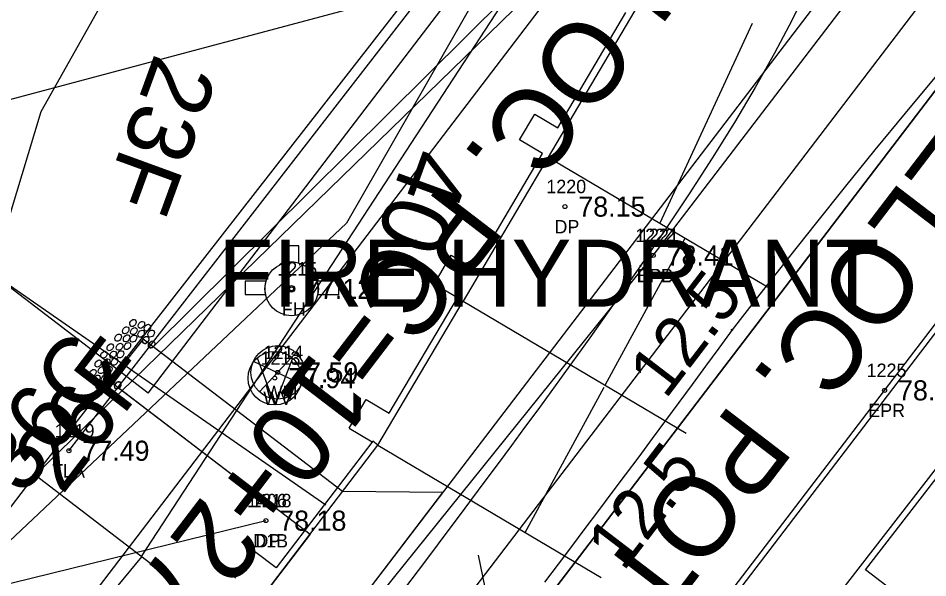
# Model space of a CAD drawing. Extents: x 2500794 to 2511032, y 910653 to 917533.
# Drawn here: x 2506136.2 to 2506204.2, y 913995.8 to 914037.6 of the extents above; entities that cross this region are included whole.
import ezdxf

# ---------------------------------------------------------------- set-up
doc = ezdxf.new("R2010")
doc.units = 0
for name, color, linetype in [('Default', 7, 'Continuous'), ('RD_EX_Driveway', 7, 'Continuous'), ('RD_EX_Driveway_txCode', 7, 'Continuous'), ('RD_EX_H2O_txCode', 7, 'Continuous'), ('RD_EX_Road', 7, 'Continuous'), ('RD_EX_Road_txCode', 7, 'Continuous'), ('RD_EX_RW', 7, 'Continuous'), ('RD_EX_TX_Driveway_ELEV', 7, 'Continuous'), ('RD_EX_TX_Road_ELEV', 7, 'Continuous'), ('RD_EX_TX_UT_ELEV', 7, 'Continuous'), ('RD_EX_TX_VEG_ELEV', 7, 'Continuous'), ('RD_EX_UT', 7, 'Continuous'), ('RD_EX_UT_txCode', 7, 'Continuous'), ('RD_EX_VEG', 7, 'Continuous'), ('RD_EX_VEG_txCode', 7, 'Continuous'), ('RD_HC_Cl', 7, 'Continuous'), ('RD_HC_Data_Rel', 7, 'Continuous'), ('RD_HC_Data_Tic', 7, 'Continuous'), ('RD_PD_ALT1_TnTmp', 7, 'Continuous'), ('RD_PD_ALT1_TrvlWay', 7, 'Continuous'), ('RD_PD_CstnLmt', 7, 'Continuous'), ('RD_PD_CstnLmt_TX', 7, 'Continuous'), ('RD_PD_Detour', 7, 'Continuous'), ('RD_PD_GR', 7, 'Continuous'), ('RD_PD_MedBWall', 7, 'Continuous'), ('RD_PD_PaintMed', 7, 'Continuous'), ('RD_PD_PaveShd', 7, 'Continuous'), ('RD_PD_Signals', 7, 'Continuous'), ('RD_Sketch10', 7, 'Continuous'), ('RD_SMD_Locator', 7, 'Continuous')]:
    doc.layers.add(name, color=color, linetype=linetype)

# ---------------------------------------------------------------- blocks, each defined once
blk = doc.blocks.new('POINT_DISPLAY')
at = {"layer": 'Default'}
blk.add_line((0, 0), (0, 0), dxfattribs=at)

msp = doc.modelspace()

# ---------------------------------------------------------------- linework, layer by layer
at = {"layer": 'RD_EX_Driveway'}
msp.add_lwpolyline([(2505985.767, 913963.589), (2506043.743, 913975.78), (2506109.597, 913989.049), (2506154.744, 914000.103)], dxfattribs=at)
at = {"layer": 'RD_EX_H2O_txCode'}
msp.add_lwpolyline([(2506111.845, 914025.213), (2506191.122, 914046.339), (2506240.906, 914108.602), (2506304.096, 914190.052), (2506361.191, 914264.825), (2506427.45, 914348.312), (2506450.333, 914379.52)], dxfattribs=at)
at = {"layer": 'RD_EX_Road'}
for points in [[(2506114.007, 913933.801), (2506123.607, 913945.349), (2506183.697, 914019.9), (2506246.754, 914102.24), (2506309.518, 914184.625), (2506366.784, 914260.378), (2506431.546, 914345.252), (2506455.95, 914376.736), (2506469.753, 914395.23), (2506492.702, 914425.08), (2506555.841, 914508.256), (2506617.748, 914589.016), (2506679.77, 914670.808), (2506740.348, 914750.219)], [(2506132.308, 913920.136), (2506200.992, 914009.83), (2506228.777, 914046.137), (2506238.188, 914058.362), (2506261.832, 914089.97), (2506324.496, 914172.224), (2506382.844, 914247.971), (2506424.88, 914303.725), (2506446.395, 914331.894), (2506508.342, 914413.092), (2506571.207, 914495.532), (2506633.007, 914576.806), (2506694.833, 914657.947), (2506756.779, 914739.179)]]:
    msp.add_lwpolyline(points, dxfattribs=at)
at = {"layer": 'RD_EX_RW'}
for q in [(2506722.671, 914763.958), (2506112.584, 914035.129)]:
    msp.add_line((2506145.95, 914009.619), q, dxfattribs=at)
at = {"layer": 'RD_EX_UT'}
for p, q in [((2506156.208, 914020.626), (2506156.208, 914019.352)), ((2506157.208, 914020.626), (2506156.208, 914020.626)), ((2506157.208, 914019.33), (2506157.208, 914020.626)), ((2506154.749, 914017.979), (2506153.192, 914017.979)), ((2506153.192, 914017.979), (2506153.192, 914016.979)), ((2506160.192, 914017.979), (2506158.581, 914017.979)), ((2506160.192, 914016.979), (2506160.192, 914017.979)), ((2506153.192, 914016.979), (2506154.711, 914016.979)), ((2506158.619, 914016.979), (2506160.192, 914016.979)), ((2506154.279, 914009.714), (2506156.946, 914012.611)), ((2506153.797, 914012.01), (2506157.428, 914010.297)), ((2506155.41, 914008.749), (2506154.106, 914012.232)), ((2506155.41, 914008.749), (2506156.732, 914012.194))]:
    msp.add_line(p, q, dxfattribs=at)
for centre, radius in [((2506156.665, 914017.405), 2), ((2506156.665, 914017.405), 0.25), ((2506155.41, 914010.742), 2), ((2506155.631, 914011.172), 2)]:
    msp.add_circle(centre, radius, dxfattribs=at)
for start, end in [(74.24553, 103.21276), (163.3387, 192.31502), (347.68498, 16.6613)]:
    msp.add_arc((2506156.665, 914017.405), 2, start, end, dxfattribs=at)
at = {"layer": 'RD_EX_VEG'}
msp.add_line((2506140.026, 914005.323), (2506726.018, 914761.038), dxfattribs=at)
at = {"layer": 'RD_HC_Cl'}
msp.add_line((2505807.568, 913512.69), (2506748.887, 914743.915), dxfattribs=at)
at = {"layer": 'RD_HC_Data_Rel'}
for p, q in [((2506234.439, 914115.768), (2506136.125, 913987.174)), ((2506256.026, 914099.264), (2506153.676, 913965.392))]:
    msp.add_line(p, q, dxfattribs=at)
at = {"layer": 'RD_HC_Data_Tic'}
msp.add_line((2506172.262, 913989.702), (2506170.643, 913997.537), dxfattribs=at)
at = {"layer": 'RD_PD_ALT1_TnTmp'}
msp.add_line((2506206.922, 914042.959), (2506137.76, 913952.5), dxfattribs=at)
for points in [[(2506195.176, 914039.741), (2506194.051, 914037.443), (2506192.759, 914034.994), (2506191.32, 914032.442), (2506189.763, 914029.825), (2506188.109, 914027.171), (2506186.377, 914024.497), (2506184.584, 914021.812), (2506182.742, 914019.124)], [(2506204.865, 914033.338), (2506202.532, 914030.534), (2506200.269, 914027.783), (2506198.062, 914025.065), (2506195.9, 914022.369), (2506193.772, 914019.687), (2506191.669, 914017.014), (2506189.585, 914014.347)], [(2506182.742, 914019.124), (2506181.806, 914017.78), (2506180.861, 914016.436), (2506179.909, 914015.092), (2506178.95, 914013.75), (2506177.985, 914012.408), (2506177.015, 914011.067), (2506176.04, 914009.727), (2506175.06, 914008.388), (2506174.077, 914007.05), (2506173.091, 914005.713), (2506172.102, 914004.376), (2506171.11, 914003.041), (2506170.115, 914001.706), (2506169.119, 914000.372), (2506168.12, 913999.038), (2506167.12, 913997.705), (2506166.119, 913996.373), (2506165.116, 913995.041)], [(2506189.585, 914014.347), (2506188.591, 914012.987), (2506187.6, 914011.629), (2506186.606, 914010.274), (2506185.61, 914008.921), (2506184.611, 914007.571), (2506183.612, 914006.224), (2506182.61, 914004.879), (2506181.608, 914003.536), (2506180.604, 914002.194), (2506179.599, 914000.854), (2506178.593, 913999.516), (2506177.586, 913998.179), (2506176.579, 913996.843), (2506175.571, 913995.508)]]:
    msp.add_lwpolyline(points, dxfattribs=at)
for centre in [(2506182.742, 914019.124), (2506182.742, 914019.124), (2506189.585, 914014.347), (2506189.585, 914014.347)]:
    msp.add_circle(centre, 0.0417, dxfattribs=at)
at = {"layer": 'RD_PD_ALT1_TrvlWay'}
for p, q in [((2506162.951, 913959.412), (2506387.409, 914252.999)), ((2506145.473, 913972.774), (2506215.723, 914064.66))]:
    msp.add_line(p, q, dxfattribs=at)
at = {"layer": 'RD_PD_CstnLmt'}
for p, q in [((2506137.493, 914003.497), (2506201.117, 914085.014)), ((2506129.005, 913992.395), (2506137.493, 914003.497))]:
    msp.add_line(p, q, dxfattribs=at)
at = {"layer": 'RD_PD_Detour'}
for p, q in [((2506186.504, 914067.21), (2506160.76, 914022.308)), ((2506160.76, 914022.308), (2506129.005, 913992.395))]:
    msp.add_line(p, q, dxfattribs=at)
at = {"layer": 'RD_PD_GR'}
for p, q in [((2506206.65, 914079.342), (2506175.845, 914027.251)), ((2506176.567, 914029.438), (2506181.657, 914038.045)), ((2506227.232, 914032.893), (2506190.129, 913985.083)), ((2506173.693, 914028.523), (2506174.839, 914030.46)), ((2506174.839, 914030.46), (2506176.567, 914029.438)), ((2506175.422, 914027.501), (2506173.693, 914028.523)), ((2506175.845, 914027.251), (2506169.483, 914016.491)), ((2506170.332, 914018.893), (2506175.422, 914027.501)), ((2506167.331, 914017.764), (2506168.603, 914019.916)), ((2506168.603, 914019.916), (2506170.332, 914018.893)), ((2506169.059, 914016.742), (2506167.331, 914017.764)), ((2506163.969, 914008.134), (2506169.059, 914016.742)), ((2506163.12, 914005.732), (2506169.483, 914016.491)), ((2506160.968, 914007.004), (2506162.241, 914009.156)), ((2506162.241, 914009.156), (2506163.969, 914008.134)), ((2506160.968, 914007.004), (2506162.694, 914005.984)), ((2506162.731, 914006.032), (2506155.501, 913996.577)), ((2506163.12, 914005.732), (2506162.729, 914006.03)), ((2506140.707, 913976.418), (2506163.12, 914005.732)), ((2506199.56, 913996.434), (2506205.691, 914004.334)), ((2506153.906, 913997.797), (2506152.388, 913995.811)), ((2506155.501, 913996.577), (2506153.906, 913997.797)), ((2506201.147, 913995.203), (2506199.56, 913996.434))]:
    msp.add_line(p, q, dxfattribs=at)
at = {"layer": 'RD_PD_MedBWall'}
msp.add_line((2505954.484, 914143.156), (2506159.214, 914001.293), dxfattribs=at)
at = {"layer": 'RD_PD_PaintMed'}
for p, q in [((2506279.06, 914144.645), (2506146.33, 914013.08)), ((2506137.493, 914003.497), (2506268.772, 914131.14)), ((2506191.095, 914037.207), (2506184.188, 914022.317)), ((2506175.845, 914027.251), (2506192.53, 914017.384)), ((2506180.132, 914010.279), (2506186.074, 914021.202)), ((2506169.483, 914016.491), (2506186.168, 914006.625)), ((2506174.12, 913999.227), (2506180.024, 914010.081)), ((2506163.12, 914005.732), (2506179.805, 913995.865)), ((2506166.092, 913981.632), (2506137.493, 914003.497))]:
    msp.add_line(p, q, dxfattribs=at)
at = {"layer": 'RD_PD_PaveShd'}
for p, q in [((2506145.575, 914013.657), (2506143.084, 914010.526)), ((2506145.53, 914013.601), (2506143.297, 914010.794)), ((2506160.472, 914002.268), (2506145.575, 914013.657)), ((2506146, 914013.332), (2506145.888, 914013.418)), ((2506160.472, 914002.268), (2506146.33, 914013.08)), ((2506143.084, 914010.526), (2506158.042, 913999.09)), ((2506143.339, 914010.331), (2506143.454, 914010.244)), ((2506143.77, 914010.002), (2506158.042, 913999.09)), ((2506145.473, 913972.774), (2506167.97, 914002.2)), ((2506145.473, 913972.774), (2506167.97, 914002.2)), ((2506167.97, 914002.2), (2506160.472, 914002.268)), ((2506167.97, 914002.2), (2506160.472, 914002.268)), ((2506140.707, 913976.418), (2506158.042, 913999.09))]:
    msp.add_line(p, q, dxfattribs=at)
msp.add_lwpolyline([(2506158.042, 913999.09), (2506150.28, 913988.938), (2506140.707, 913976.418)], dxfattribs=at)
for centre, start_param, end_param in [((2506145.76, 914013.593), 5.179438, 7.625001), ((2506146.202, 914013.256), 4.916821, 7.620407), ((2506143.237, 914010.53), 1.21821, 3.672072), ((2506143.674, 914010.206), 1.189396, 5.064647)]:
    msp.add_ellipse(centre, major_axis=(-0.17, -0.232), ratio=0.739412, start_param=start_param, end_param=end_param, dxfattribs=at)
at = {"layer": 'RD_PD_Signals'}
for p, q in [((2506176.833, 914100.024), (2506137.936, 914030.621)), ((2506145.437, 913997.424), (2506200.298, 914081.358)), ((2506137.936, 914030.621), (2506122.027, 913978.4)), ((2506121.381, 913968.637), (2506145.479, 913997.392))]:
    msp.add_line(p, q, dxfattribs=at)
at = {"layer": 'RD_Sketch10'}
for centre in [(2506144.272, 914014.316), (2506144.812, 914014.859), (2506145.441, 914014.72), (2506145.885, 914014.502), (2506143.704, 914013.767), (2506144.333, 914013.718), (2506144.854, 914013.695), (2506144.873, 914014.252), (2506145.417, 914014.057), (2506146.168, 914014.067), (2506143.111, 914013.051), (2506143.805, 914013.082), (2506144.392, 914013.136), (2506145.76, 914013.593), (2506146.202, 914013.256), (2506142.642, 914012.486), (2506143.323, 914012.499), (2506143.879, 914012.518), (2506142.215, 914011.835), (2506142.851, 914011.93), (2506143.426, 914011.971), (2506141.817, 914011.137), (2506142.459, 914011.34), (2506143.003, 914011.362), (2506142.116, 914010.709), (2506142.687, 914010.7), (2506143.237, 914010.53), (2506143.674, 914010.206), (2506142.29, 914010.189), (2506142.819, 914010.04)]:
    msp.add_ellipse(centre, major_axis=(-0.17, -0.232), ratio=0.739412, dxfattribs=at)
at = {"layer": 'RD_SMD_Locator'}
for centre in [(2506177.094, 914023.549), (2506183.697, 914019.9), (2506183.697, 914019.9), (2506156.665, 914017.405), (2506155.631, 914011.172), (2506155.41, 914010.742), (2506200.992, 914009.83), (2506140.026, 914005.323), (2506154.744, 914000.103), (2506154.744, 914000.103)]:
    msp.add_circle(centre, 0.15, dxfattribs=at)

# ---------------------------------------------------------------- block references
at = {"layer": 'Default', "xscale": 3.937007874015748, "yscale": 3.937007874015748}
msp.add_blockref('POINT_DISPLAY', (2506151.202, 914016.076), dxfattribs=at)
msp.add_blockref('POINT_DISPLAY', (2506151.202, 914016.076), dxfattribs=at)

# ---------------------------------------------------------------- texts
at = {"layer": 'Default'}
msp.add_text('FIRE HYDRANT', height=5, dxfattribs=at).set_placement((2506151.202, 914016.076))
msp.add_text('FIRE HYDRANT', height=5, dxfattribs=at).set_placement((2506151.202, 914016.076))
at = {"layer": 'RD_EX_Driveway_txCode'}
for s, p in [('1220', (2506175.708, 914024.549)), ('DP', (2506176.314, 914021.549)), ('1221', (2506182.634, 914020.9)), ('DPB', (2506182.445, 914017.9)), ('1406', (2506153.335, 914001.103)), ('1218', (2506153.681, 914001.103)), ('D1B', (2506153.799, 913998.103)), ('DP', (2506153.965, 913998.103))]:
    msp.add_text(s, height=1, dxfattribs=at).set_placement(p)
at = {"layer": 'RD_EX_Road_txCode'}
for s, p in [('1222', (2506182.35, 914020.9)), ('EPL', (2506182.492, 914017.9)), ('1225', (2506199.646, 914010.83)), ('EPR', (2506199.764, 914007.83))]:
    msp.add_text(s, height=1, dxfattribs=at).set_placement(p)
at = {"layer": 'RD_EX_TX_Driveway_ELEV'}
for s, p in [('78.15', (2506178.094, 914022.799)), ('78.41', (2506184.697, 914019.15)), ('78.18', (2506155.744, 913999.353)), ('78.18', (2506155.744, 913999.353))]:
    msp.add_text(s, height=1.5, dxfattribs=at).set_placement(p)
at = {"layer": 'RD_EX_TX_Road_ELEV'}
for s, p in [('78.41', (2506184.697, 914019.15)), ('78.25', (2506201.992, 914009.08))]:
    msp.add_text(s, height=1.5, dxfattribs=at).set_placement(p)
at = {"layer": 'RD_EX_TX_UT_ELEV'}
for s, p in [('77.12', (2506157.665, 914016.655)), ('77.59', (2506156.631, 914010.422)), ('77.94', (2506156.41, 914009.992))]:
    msp.add_text(s, height=1.5, dxfattribs=at).set_placement(p)
at = {"layer": 'RD_EX_TX_VEG_ELEV'}
msp.add_text('77.49', height=1.5, dxfattribs=at).set_placement((2506141.026, 914004.573))
at = {"layer": 'RD_EX_UT_txCode'}
for s, p in [('1215', (2506155.602, 914018.405)), ('FH', (2506155.933, 914015.405)), ('1213', (2506154.347, 914011.742)), ('1214', (2506154.568, 914012.172)), ('WM', (2506154.725, 914009.172)), ('WV', (2506154.552, 914008.742))]:
    msp.add_text(s, height=1, dxfattribs=at).set_placement(p)
at = {"layer": 'RD_EX_VEG_txCode'}
for s, p in [('1219', (2506138.963, 914006.323)), ('TLA', (2506138.766, 914003.323))]:
    msp.add_text(s, height=1, dxfattribs=at).set_placement(p)
at = {"layer": 'RD_HC_Data_Rel'}
for s, p in [('RELOC. PC=10+27.17', (2506187.439, 914050.999)), ('RELOC. POT=10+00.00', (2506209.026, 914034.495))]:
    msp.add_text(s, height=6, rotation=232.60071, dxfattribs=at).set_placement(p)
at = {"layer": 'RD_PD_CstnLmt_TX'}
msp.add_text('36C', height=5, rotation=52.60071, dxfattribs=at).set_placement((2506136.583, 914001.853))
at = {"layer": 'RD_PD_Detour'}
msp.add_text('40C', height=5, rotation=249.98651, dxfattribs=at).set_placement((2506165.475, 914028.216))
at = {"layer": 'RD_PD_PaintMed'}
for p in [(2506184.613, 914009.097), (2506181.457, 913996.234)]:
    msp.add_text('12.5', height=3.75, rotation=52.60071, dxfattribs=at).set_placement(p)
at = {"layer": 'RD_PD_Signals'}
for s, rotation, p in [('23F', 249.98651, (2506146.486, 914035.102)), ('26F', 52.60071, (2506139.52, 914001.947))]:
    msp.add_text(s, height=5, rotation=rotation, dxfattribs=at).set_placement(p)

doc.saveas('drawing.dxf')
